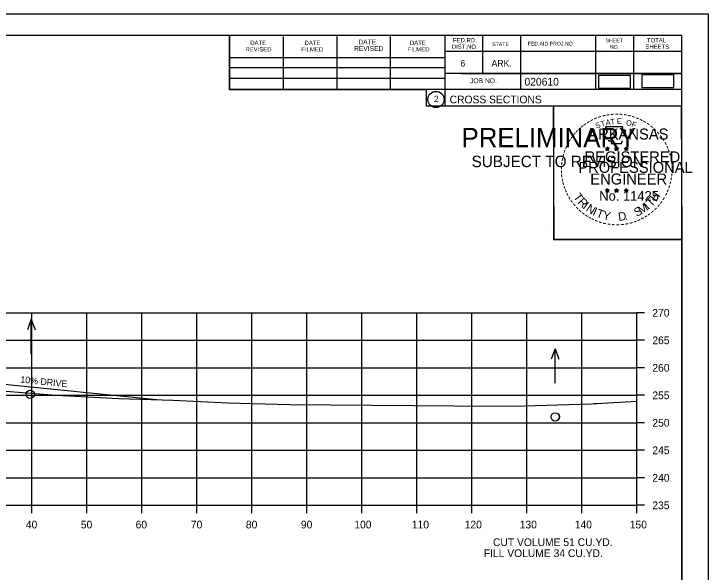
# Model space of a CAD drawing. Extents: x 1103485 to 1107180, y 2010593 to 2011873.
# Drawn here: x 1107053.9 to 1107180.1, y 2011344.7 to 2011446.2 of the extents above; entities that cross this region are included whole.
import ezdxf

# ---------------------------------------------------------------- set-up
doc = ezdxf.new("R2010")
doc.units = 0
for name, color, linetype in [('R_Axis', 7, 'Continuous'), ('R_Axis Annot', 7, 'Continuous'), ('R_Border', 7, 'Continuous'), ('R_Border PE', 7, 'Continuous'), ('R_Border Prem', 7, 'Continuous'), ('R_Drive', 7, 'Continuous'), ('R_Exist Surface', 7, 'Continuous'), ('R_Grid', 7, 'Continuous'), ('R_No Plot', 7, 'Continuous'), ('R_Water', 7, 'Continuous'), ('R_Water Annot', 7, 'Continuous')]:
    doc.layers.add(name, color=color, linetype=linetype)

msp = doc.modelspace()

# ---------------------------------------------------------------- linework, layer by layer
at = {"layer": 'R_Axis'}
for p, q in [((1107167.18, 2011356.83), (1107167.18, 2011391.83)), ((1107168.58, 2011391.83), (1107167.18, 2011391.83)), ((1107168.58, 2011386.83), (1107167.18, 2011386.83)), ((1107168.58, 2011381.83), (1107167.18, 2011381.83)), ((1107168.58, 2011376.83), (1107167.18, 2011376.83)), ((1107168.58, 2011371.83), (1107167.18, 2011371.83)), ((1107168.58, 2011366.83), (1107167.18, 2011366.83)), ((1107168.58, 2011361.83), (1107167.18, 2011361.83)), ((1106867.18, 2011356.83), (1107167.18, 2011356.83)), ((1107057.18, 2011355.43), (1107057.18, 2011356.83)), ((1107067.18, 2011355.43), (1107067.18, 2011356.83)), ((1107077.18, 2011355.43), (1107077.18, 2011356.83)), ((1107087.18, 2011355.43), (1107087.18, 2011356.83)), ((1107097.18, 2011355.43), (1107097.18, 2011356.83)), ((1107107.18, 2011355.43), (1107107.18, 2011356.83)), ((1107117.18, 2011355.43), (1107117.18, 2011356.83)), ((1107127.18, 2011355.43), (1107127.18, 2011356.83)), ((1107137.18, 2011355.43), (1107137.18, 2011356.83)), ((1107147.18, 2011355.43), (1107147.18, 2011356.83)), ((1107157.18, 2011355.43), (1107157.18, 2011356.83)), ((1107167.18, 2011355.43), (1107167.18, 2011356.83)), ((1107168.58, 2011356.83), (1107167.18, 2011356.83))]:
    msp.add_line(p, q, dxfattribs=at)
at = {"layer": 'R_Border'}
for p, q in [((1106859.18, 2011442.29), (1107175.36, 2011442.29)), ((1107093.1, 2011432.41), (1107093.1, 2011442.29)), ((1107102.96, 2011432.41), (1107102.96, 2011442.09)), ((1107112.72, 2011432.41), (1107112.72, 2011442.09)), ((1107122.4, 2011432.41), (1107122.4, 2011442.09)), ((1107132.26, 2011442.29), (1107132.26, 2011429.49)), ((1107139.1, 2011442.29), (1107139.1, 2011435.35)), ((1107146.04, 2011442.29), (1107146.04, 2011432.41)), ((1107159.62, 2011442.29), (1107159.62, 2011432.41)), ((1107166.56, 2011442.29), (1107166.56, 2011432.41)), ((1107175.36, 2011236.83), (1107175.36, 2011442.29)), ((1107175.36, 2011439.35), (1107132.26, 2011439.35)), ((1107175.36, 2011439.37), (1107175.36, 2011439.37)), ((1107093.1, 2011438.27), (1107132.26, 2011438.27)), ((1107093.1, 2011436.41), (1107132.26, 2011436.41)), ((1107175.36, 2011435.35), (1107132.26, 2011435.35)), ((1107135.22, 2011435.35), (1107175.36, 2011435.35)), ((1107093.1, 2011432.41), (1107093.1, 2011434.47)), ((1107093.1, 2011434.47), (1107132.26, 2011434.47)), ((1107175.36, 2011432.41), (1107093.1, 2011432.41)), ((1107132.26, 2011429.49), (1107175.36, 2011429.49))]:
    msp.add_line(p, q, dxfattribs=at)
msp.add_circle((1107130.65, 2011430.63), 1.47, dxfattribs=at)
at = {"layer": 'R_Border PE'}
for p, q in [((1107161.45, 2011421.75), (1107161.8, 2011421.63)), ((1107161.45, 2011421.75), (1107161.7, 2011421.7)), ((1107161.45, 2011421.75), (1107161.69, 2011421.62)), ((1107161.58, 2011421.34), (1107161.8, 2011421.63)), ((1107161.58, 2011421.34), (1107161.71, 2011421.58)), ((1107161.58, 2011421.34), (1107161.8, 2011421.55)), ((1107161.8, 2011422), (1107161.76, 2011421.75)), ((1107161.8, 2011421.63), (1107161.8, 2011422)), ((1107161.8, 2011422), (1107161.85, 2011421.75)), ((1107162.14, 2011421.75), (1107161.8, 2011421.63)), ((1107162.01, 2011421.34), (1107161.8, 2011421.63)), ((1107162.01, 2011421.34), (1107161.8, 2011421.55)), ((1107162.14, 2011421.75), (1107161.86, 2011421.7)), ((1107162.01, 2011421.34), (1107161.87, 2011421.63)), ((1107162.14, 2011421.75), (1107161.94, 2011421.64)), ((1107163.12, 2011421.75), (1107163.47, 2011421.63)), ((1107163.12, 2011421.75), (1107163.37, 2011421.7)), ((1107163.12, 2011421.75), (1107163.36, 2011421.62)), ((1107163.25, 2011421.34), (1107163.47, 2011421.63)), ((1107163.25, 2011421.34), (1107163.38, 2011421.58)), ((1107163.25, 2011421.34), (1107163.47, 2011421.55)), ((1107163.47, 2011422), (1107163.43, 2011421.75)), ((1107163.47, 2011421.63), (1107163.47, 2011422)), ((1107163.47, 2011422), (1107163.52, 2011421.75)), ((1107163.81, 2011421.75), (1107163.47, 2011421.63)), ((1107163.68, 2011421.34), (1107163.47, 2011421.63)), ((1107163.68, 2011421.34), (1107163.47, 2011421.55)), ((1107163.81, 2011421.75), (1107163.53, 2011421.7)), ((1107163.68, 2011421.34), (1107163.54, 2011421.63)), ((1107163.81, 2011421.75), (1107163.61, 2011421.64)), ((1107164.88, 2011421.73), (1107165.23, 2011421.62)), ((1107164.88, 2011421.73), (1107165.14, 2011421.69)), ((1107164.88, 2011421.73), (1107165.12, 2011421.61)), ((1107165.02, 2011421.33), (1107165.23, 2011421.62)), ((1107165.02, 2011421.33), (1107165.14, 2011421.57)), ((1107165.02, 2011421.33), (1107165.23, 2011421.54)), ((1107165.23, 2011421.99), (1107165.19, 2011421.74)), ((1107165.23, 2011421.62), (1107165.23, 2011421.99)), ((1107165.23, 2011421.99), (1107165.28, 2011421.74)), ((1107165.58, 2011421.73), (1107165.23, 2011421.62)), ((1107165.44, 2011421.33), (1107165.23, 2011421.62)), ((1107165.44, 2011421.33), (1107165.23, 2011421.54)), ((1107165.58, 2011421.73), (1107165.29, 2011421.68)), ((1107165.44, 2011421.33), (1107165.31, 2011421.62)), ((1107165.58, 2011421.73), (1107165.37, 2011421.63)), ((1107161.44, 2011414.17), (1107161.79, 2011414.06)), ((1107161.44, 2011414.17), (1107161.7, 2011414.13)), ((1107161.44, 2011414.17), (1107161.68, 2011414.05)), ((1107161.58, 2011413.76), (1107161.79, 2011414.06)), ((1107161.58, 2011413.76), (1107161.7, 2011414.01)), ((1107161.58, 2011413.76), (1107161.79, 2011413.98)), ((1107161.79, 2011414.43), (1107161.75, 2011414.17)), ((1107161.79, 2011414.06), (1107161.79, 2011414.43)), ((1107161.79, 2011414.43), (1107161.84, 2011414.18)), ((1107162.14, 2011414.17), (1107161.79, 2011414.06)), ((1107162.01, 2011413.76), (1107161.79, 2011414.06)), ((1107162.01, 2011413.76), (1107161.79, 2011413.98)), ((1107162.14, 2011414.17), (1107161.85, 2011414.12)), ((1107162.01, 2011413.76), (1107161.87, 2011414.06)), ((1107162.14, 2011414.17), (1107161.94, 2011414.07)), ((1107163.11, 2011414.17), (1107163.46, 2011414.06)), ((1107163.11, 2011414.17), (1107163.37, 2011414.13)), ((1107163.11, 2011414.17), (1107163.35, 2011414.05)), ((1107163.25, 2011413.76), (1107163.46, 2011414.06)), ((1107163.25, 2011413.76), (1107163.37, 2011414.01)), ((1107163.25, 2011413.76), (1107163.46, 2011413.98)), ((1107163.46, 2011414.43), (1107163.42, 2011414.17)), ((1107163.46, 2011414.06), (1107163.46, 2011414.43)), ((1107163.46, 2011414.43), (1107163.51, 2011414.18)), ((1107163.81, 2011414.17), (1107163.46, 2011414.06)), ((1107163.68, 2011413.76), (1107163.46, 2011414.06)), ((1107163.68, 2011413.76), (1107163.46, 2011413.98)), ((1107163.81, 2011414.17), (1107163.52, 2011414.12)), ((1107163.68, 2011413.76), (1107163.54, 2011414.06)), ((1107163.81, 2011414.17), (1107163.61, 2011414.07)), ((1107164.88, 2011414.16), (1107165.23, 2011414.05)), ((1107164.88, 2011414.16), (1107165.13, 2011414.12)), ((1107164.88, 2011414.16), (1107165.12, 2011414.04)), ((1107165.01, 2011413.75), (1107165.23, 2011414.05)), ((1107165.01, 2011413.75), (1107165.14, 2011414)), ((1107165.01, 2011413.75), (1107165.23, 2011413.97)), ((1107165.23, 2011414.42), (1107165.19, 2011414.16)), ((1107165.23, 2011414.05), (1107165.23, 2011414.42)), ((1107165.23, 2011414.42), (1107165.28, 2011414.17)), ((1107165.58, 2011414.16), (1107165.23, 2011414.05)), ((1107165.44, 2011413.75), (1107165.23, 2011414.05)), ((1107165.44, 2011413.75), (1107165.23, 2011413.97)), ((1107165.58, 2011414.16), (1107165.29, 2011414.11)), ((1107165.44, 2011413.75), (1107165.31, 2011414.05)), ((1107165.58, 2011414.16), (1107165.37, 2011414.06))]:
    msp.add_line(p, q, dxfattribs=at)
for points in [[(1107161.49, 2011425.62), (1107161.76, 2011424.8)], [(1107165, 2011424.7), (1107165.14, 2011424.99), (1107164.46, 2011424.96), (1107164.61, 2011425.62), (1107161.49, 2011425.62)], [(1107161.98, 2011423.2), (1107161.98, 2011423.11), (1107162.54, 2011423.09), (1107162.49, 2011422.62), (1107164.36, 2011422.62), (1107164.56, 2011423.16)], [(1107161.8, 2011422), (1107162.01, 2011421.34), (1107161.45, 2011421.75), (1107162.14, 2011421.75), (1107161.58, 2011421.34), (1107161.8, 2011422)], [(1107163.47, 2011422), (1107163.68, 2011421.34), (1107163.12, 2011421.75), (1107163.81, 2011421.75), (1107163.25, 2011421.34), (1107163.47, 2011422)], [(1107165.23, 2011421.99), (1107165.44, 2011421.33), (1107164.88, 2011421.73), (1107165.58, 2011421.73), (1107165.02, 2011421.33), (1107165.23, 2011421.99)], [(1107161.79, 2011414.43), (1107162.01, 2011413.76), (1107161.44, 2011414.17), (1107162.14, 2011414.17), (1107161.58, 2011413.76), (1107161.79, 2011414.43)], [(1107163.46, 2011414.43), (1107163.68, 2011413.76), (1107163.11, 2011414.17), (1107163.81, 2011414.17), (1107163.25, 2011413.76), (1107163.46, 2011414.43)], [(1107165.23, 2011414.42), (1107165.44, 2011413.75), (1107164.88, 2011414.16), (1107165.58, 2011414.16), (1107165.01, 2011413.75), (1107165.23, 2011414.42)]]:
    msp.add_lwpolyline(points, dxfattribs=at)
for centre, radius in [((1107161.8, 2011421.63), 0.172), ((1107161.8, 2011421.63), 0.145), ((1107161.8, 2011421.63), 0.116), ((1107161.8, 2011421.63), 0.0991), ((1107161.8, 2011421.63), 0.0747), ((1107161.8, 2011421.63), 0.0495), ((1107161.8, 2011421.63), 0.0296), ((1107163.47, 2011421.63), 0.172), ((1107163.47, 2011421.63), 0.145), ((1107163.47, 2011421.63), 0.116), ((1107163.47, 2011421.63), 0.0991), ((1107163.47, 2011421.63), 0.0747), ((1107163.47, 2011421.63), 0.0495), ((1107163.47, 2011421.63), 0.0296), ((1107165.23, 2011421.62), 0.172), ((1107165.23, 2011421.62), 0.145), ((1107165.23, 2011421.62), 0.116), ((1107165.23, 2011421.62), 0.0991), ((1107165.23, 2011421.62), 0.0747), ((1107165.23, 2011421.62), 0.0495), ((1107165.23, 2011421.62), 0.0296), ((1107161.79, 2011414.06), 0.172), ((1107161.79, 2011414.06), 0.145), ((1107161.79, 2011414.06), 0.116), ((1107161.79, 2011414.06), 0.0991), ((1107161.79, 2011414.06), 0.0747), ((1107161.79, 2011414.06), 0.0495), ((1107161.79, 2011414.06), 0.0296), ((1107163.46, 2011414.06), 0.172), ((1107163.46, 2011414.06), 0.145), ((1107163.46, 2011414.06), 0.116), ((1107163.46, 2011414.06), 0.0991), ((1107163.46, 2011414.06), 0.0747), ((1107163.46, 2011414.06), 0.0495), ((1107163.46, 2011414.06), 0.0296), ((1107165.23, 2011414.05), 0.172), ((1107165.23, 2011414.05), 0.145), ((1107165.23, 2011414.05), 0.116), ((1107165.23, 2011414.05), 0.0991), ((1107165.23, 2011414.05), 0.0747), ((1107165.23, 2011414.05), 0.0495), ((1107165.23, 2011414.05), 0.0296)]:
    msp.add_circle(centre, radius, dxfattribs=at)
at = {"layer": 'R_Drive'}
msp.add_line((1107048.15, 2011379.23), (1107079.85, 2011376.06), dxfattribs=at)
at = {"layer": 'R_Exist Surface'}
msp.add_lwpolyline([(1107052.48, 2011377.58), (1107061.61, 2011376.83), (1107073.02, 2011376.26), (1107082.8, 2011375.98), (1107092.86, 2011375.49), (1107104.07, 2011375.18), (1107111.47, 2011375.09), (1107118.92, 2011375.06), (1107126.74, 2011374.96), (1107133.89, 2011374.94), (1107144.71, 2011374.88), (1107148.68, 2011374.96), (1107158.92, 2011375.31), (1107159.41, 2011375.33), (1107159.82, 2011375.36), (1107159.9, 2011375.37), (1107167.18, 2011375.79)], dxfattribs=at)
at = {"layer": 'R_Grid'}
for p, q in [((1106867.18, 2011391.83), (1107167.18, 2011391.83)), ((1107057.18, 2011356.83), (1107057.18, 2011391.83)), ((1107067.18, 2011356.83), (1107067.18, 2011391.83)), ((1107077.18, 2011356.83), (1107077.18, 2011391.83)), ((1107087.18, 2011356.83), (1107087.18, 2011391.83)), ((1107097.18, 2011356.83), (1107097.18, 2011391.83)), ((1107107.18, 2011356.83), (1107107.18, 2011391.83)), ((1107117.18, 2011356.83), (1107117.18, 2011391.83)), ((1107127.18, 2011356.83), (1107127.18, 2011391.83)), ((1107137.18, 2011356.83), (1107137.18, 2011391.83)), ((1107147.18, 2011356.83), (1107147.18, 2011391.83)), ((1107157.18, 2011356.83), (1107157.18, 2011391.83)), ((1107167.18, 2011356.83), (1107167.18, 2011391.83)), ((1106867.18, 2011386.83), (1107167.18, 2011386.83)), ((1106867.18, 2011381.83), (1107167.18, 2011381.83)), ((1106867.18, 2011376.83), (1107167.18, 2011376.83)), ((1106867.18, 2011371.83), (1107167.18, 2011371.83)), ((1106867.18, 2011366.83), (1107167.18, 2011366.83)), ((1106867.18, 2011361.83), (1107167.18, 2011361.83)), ((1106867.18, 2011356.83), (1107167.18, 2011356.83))]:
    msp.add_line(p, q, dxfattribs=at)
at = {"layer": 'R_No Plot'}
for p, q in [((1106846.78, 2011446.19), (1107180.12, 2011446.19)), ((1107151.4, 2011407.04), (1107151.4, 2011407.04))]:
    msp.add_line(p, q, dxfattribs=at)
for points in [[(1106846.78, 2011446.19), (1107180.12, 2011446.19), (1107180.12, 2011232.85), (1106846.78, 2011232.85)], [(1107093.1, 2011442.29), (1107093.1, 2011432.41), (1107128.84, 2011432.41), (1107128.84, 2011429.49), (1107152.04, 2011429.49), (1107152.04, 2011405.16), (1107175.36, 2011405.16), (1107175.36, 2011236.83), (1106859.18, 2011236.83), (1106859.18, 2011442.29)], [(1107152.04, 2011429.49), (1107175.24, 2011429.49), (1107175.36, 2011405.16), (1107152.16, 2011405.16)]]:
    msp.add_lwpolyline(points, close=True, dxfattribs=at)
at = {"layer": 'R_Water'}
for points in [[(1107168.04, 2011432.78), (1107173.87, 2011432.78), (1107173.87, 2011435.1), (1107168.04, 2011435.1)], [(1107160.2, 2011432.68), (1107166.03, 2011432.68), (1107166.03, 2011434.99), (1107160.2, 2011434.99)]]:
    msp.add_lwpolyline(points, close=True, dxfattribs=at)
for centre, radius in [((1107056.91, 2011377.02), 0.755), ((1107056.91, 2011377.02), 0.75), ((1107152.32, 2011372.91), 0.755), ((1107152.32, 2011372.91), 0.75)]:
    msp.add_circle(centre, radius, dxfattribs=at)
at = {"layer": 'R_Water Annot'}
for p, q in [((1107057.09, 2011390.65), (1107056.39, 2011388.72)), ((1107057.09, 2011384.36), (1107057.09, 2011390.65)), ((1107057.09, 2011390.65), (1107057.79, 2011388.72)), ((1107152.3, 2011385.3), (1107151.6, 2011383.38)), ((1107152.3, 2011379.02), (1107152.3, 2011385.3)), ((1107152.3, 2011385.3), (1107153, 2011383.38))]:
    msp.add_line(p, q, dxfattribs=at)

# ---------------------------------------------------------------- texts
at = {"layer": 'R_Axis Annot'}
for s, p in [('270', (1107169.98, 2011391.13)), ('265', (1107169.98, 2011386.13)), ('260', (1107169.98, 2011381.13)), ('255', (1107169.98, 2011376.13)), ('250', (1107169.98, 2011371.13)), ('245', (1107169.98, 2011366.13)), ('240', (1107169.98, 2011361.13)), ('235', (1107169.98, 2011356.13)), ('40', (1107056.1, 2011352.63)), ('50', (1107066.1, 2011352.63)), ('60', (1107076.06, 2011352.63)), ('70', (1107086.1, 2011352.63)), ('80', (1107096.1, 2011352.63)), ('90', (1107106.1, 2011352.63)), ('100', (1107115.81, 2011352.63)), ('110', (1107126.26, 2011352.63)), ('120', (1107135.87, 2011352.63)), ('130', (1107145.87, 2011352.63)), ('140', (1107155.87, 2011352.63)), ('150', (1107165.87, 2011352.63)), ('CUT VOLUME 51 CU.YD.', (1107141.01, 2011349.43)), ('FILL VOLUME 34 CU.YD.', (1107139.34, 2011347.43))]:
    msp.add_text(s, height=1.4, dxfattribs=at).set_placement(p)
at = {"layer": 'R_Border'}
for s, height, p in [('DATE', 0.879, (1107116.54, 2011440.63)), ('FED.RD.', 0.782, (1107133.74, 2011441.01)), ('SHEET', 0.684, (1107161.48, 2011441.01)), ('TOTAL', 0.782, (1107169, 2011441.01)), ('REVISED', 0.782, (1107096.02, 2011439.35)), ('DATE', 0.782, (1107096.9, 2011440.53)), ('FILMED', 0.782, (1107106.18, 2011439.35)), ('DATE', 0.782, (1107106.76, 2011440.53)), ('REVISED', 0.879, (1107115.76, 2011439.45)), ('FILMED', 0.782, (1107125.52, 2011439.35)), ('DATE', 0.782, (1107125.92, 2011440.53)), ('DIST.NO.', 0.782, (1107133.54, 2011439.83)), ('STATE', 0.684, (1107140.86, 2011440.33)), ('FED.AID PROJ.NO.', 0.684, (1107147.32, 2011440.43)), ('NO.', 0.684, (1107162.26, 2011439.83)), ('SHEETS', 0.782, (1107168.72, 2011439.83)), ('6', 1.17, (1107135.1, 2011436.61)), ('ARK.', 1.172, (1107140.76, 2011436.61)), ('JOB NO.', 0.879, (1107136.86, 2011433.59)), ('020610', 1.4, (1107146.74, 2011433.15)), ('2', 1.17, (1107130.27, 2011430.14)), ('CROSS SECTIONS', 1.4, (1107133.13, 2011429.92))]:
    msp.add_text(s, height=height, rotation=360, dxfattribs=at).set_placement(p)
at = {"layer": 'R_Border PE'}
for s, height, rotation, p in [('-', 1.6, 19.1761, (1107160.24, 2011426.75)), ('-', 1.6, 13.6301, (1107160.99, 2011426.99)), ('-', 1.6, 10.2193, (1107161.67, 2011427.15)), ('-', 1.6, 5.8968, (1107162.39, 2011427.26)), ('-', 1.6, 0.1862, (1107163.17, 2011427.34)), ('-', 1.6, 357.743, (1107163.89, 2011427.32)), ('-', 1.6, 352.1617, (1107164.63, 2011427.27)), ('-', 1.6, 347.2049, (1107165.35, 2011427.15)), ('-', 1.6, 342.3362, (1107165.99, 2011427)), ('-', 1.6, 36.2317, (1107157.8, 2011425.4)), ('-', 1.6, 34.0636, (1107158.37, 2011425.79)), ('-', 1.6, 28.7918, (1107158.97, 2011426.16)), ('-', 1.6, 24.3072, (1107159.6, 2011426.48)), ('S', 1, 21.594, (1107159.84, 2011425.3)), ('T', 1, 16.4036, (1107160.76, 2011425.63)), ('A', 1, 11.2132, (1107161.58, 2011425.88)), ('T', 1, 6.0228, (1107162.43, 2011426.05)), ('E', 1, 0.8323, (1107163.54, 2011426.16)), ('O', 1, 350.4515, (1107165.14, 2011425.95)), ('F', 1, 340.0707, (1107166.1, 2011425.72)), ('-', 1.6, 337.8551, (1107166.72, 2011426.77)), ('-', 1.6, 334.1211, (1107167.35, 2011426.5)), ('-', 1.6, 329.6409, (1107167.93, 2011426.22)), ('-', 1.6, 325.8627, (1107168.58, 2011425.86)), ('-', 1.6, 48.423, (1107156.44, 2011424.13)), ('-', 1.6, 42.9622, (1107156.89, 2011424.6)), ('-', 1.6, 38.9507, (1107157.32, 2011425.02)), ('ARKANSAS', 2, 360, (1107158.34, 2011423.34)), ('-', 1.6, 320.5297, (1107169.19, 2011425.43)), ('-', 1.6, 315.5786, (1107169.78, 2011424.95)), ('-', 1.6, 54.2325, (1107155.62, 2011423.07)), ('-', 1.6, 50.6142, (1107156.04, 2011423.64)), ('-', 1.6, 309.8797, (1107170.35, 2011424.4)), ('-', 1.6, 306.6522, (1107170.88, 2011423.79)), ('-', 1.6, 62.8713, (1107154.98, 2011421.93)), ('-', 1.6, 58.0706, (1107155.3, 2011422.55)), ('-', 1.4, 303.6753, (1107171.36, 2011423.23)), ('-', 1.6, 299.6684, (1107171.68, 2011422.62)), ('-', 1.6, 72.3945, (1107154.51, 2011420.69)), ('-', 1.6, 67.7743, (1107154.73, 2011421.32)), ('REGISTERED', 2, 360, (1107157.66, 2011419.19)), ('DWB', 0.01, 360, (1107161.78, 2011421.63)), ('DWB', 0.01, 360, (1107163.45, 2011421.63)), ('DWB', 0.01, 360, (1107165.22, 2011421.62)), ('-', 1.6, 294.6628, (1107172.01, 2011422.01)), ('-', 1.6, 290.5728, (1107172.26, 2011421.43)), ('-', 1.6, 81.2013, (1107154.18, 2011419.26)), ('-', 1.6, 75.461, (1107154.31, 2011419.98)), ('-', 1.6, 285.1233, (1107172.5, 2011420.85)), ('-', 1.6, 280.5493, (1107172.7, 2011420.11)), ('-', 1.6, 85.1863, (1107154.1, 2011418.57)), ('PROFESSIONAL', 2, 360, (1107156.52, 2011417.28)), ('-', 1.6, 276.5962, (1107172.86, 2011419.34)), ('-', 1.6, 94.1959, (1107154.11, 2011417.15)), ('-', 1.6, 89.0622, (1107154.08, 2011417.87)), ('-', 1.6, 274.3301, (1107172.92, 2011418.62)), ('-', 1.6, 269.9407, (1107172.95, 2011417.99)), ('-', 1.6, 98.9479, (1107154.18, 2011416.48)), ('-', 1.6, 101.7149, (1107154.32, 2011415.75)), ('ENGINEER', 2, 360, (1107158.7, 2011415.16)), ('-', 1.6, 260.9953, (1107172.86, 2011416.67)), ('-', 1.6, 263.5172, (1107172.94, 2011417.32)), ('-', 1.6, 105.4578, (1107154.48, 2011415.15)), ('-', 1.6, 109.0874, (1107154.7, 2011414.52)), ('-', 1.6, 252.8681, (1107172.57, 2011415.27)), ('-', 1.6, 255.7626, (1107172.75, 2011415.99)), ('-', 1.6, 114.0643, (1107154.95, 2011413.93)), ('-', 1.6, 115.7289, (1107155.25, 2011413.31)), ('T', 1.54, 306.0406, (1107155.55, 2011412.9)), ('No. 11425', 1.757, 360, (1107160.33, 2011412.21)), ('DWB', 0.01, 360, (1107161.78, 2011414.06)), ('DWB', 0.01, 360, (1107163.45, 2011414.06)), ('DWB', 0.01, 360, (1107165.22, 2011414.05)), ('H', 1.54, 54.6088, (1107170.67, 2011411.94)), ('-', 1.6, 244.6197, (1107172.09, 2011413.97)), ('-', 1.6, 247.8887, (1107172.35, 2011414.59)), ('-', 1.6, 120.4471, (1107155.61, 2011412.72)), ('-', 1.6, 125.8934, (1107156.01, 2011412.16)), ('R', 1.54, 314.005, (1107156.32, 2011411.85)), ('T', 1.54, 46.6444, (1107169.78, 2011410.99)), ('-', 1.6, 239.0712, (1107171.69, 2011413.21)), ('-', 1.6, 130.7181, (1107156.48, 2011411.61)), ('-', 1.6, 134.2238, (1107156.99, 2011411.06)), ('I', 1.54, 321.9694, (1107157.22, 2011410.92)), ('N', 1.54, 326.5002, (1107157.78, 2011410.45)), ('S', 1.54, 26.9312, (1107167.1, 2011409.26)), ('M', 1.54, 32.6563, (1107167.94, 2011409.67)), ('I', 1.54, 42.1136, (1107169.22, 2011410.51)), ('-', 1.6, 231.2538, (1107170.86, 2011411.99)), ('-', 1.6, 233.8452, (1107171.29, 2011412.56)), ('-', 1.6, 138.9338, (1107157.52, 2011410.6)), ('-', 1.6, 144.6463, (1107158.07, 2011410.19)), ('I', 1.54, 335.3603, (1107158.99, 2011409.66)), ('T', 1.54, 339.8912, (1107159.65, 2011409.34)), ('Y', 1.54, 347.8556, (1107160.87, 2011408.89)), ('D', 1.54, 6.3969, (1107163.85, 2011408.53)), ('-', 1.6, 215.7363, (1107169.31, 2011410.45)), ('-', 1.6, 221.0851, (1107169.86, 2011410.92)), ('-', 1.6, 225.7653, (1107170.38, 2011411.43)), ('-', 1.6, 148.0898, (1107158.64, 2011409.82)), ('-', 1.6, 151.5704, (1107159.21, 2011409.5)), ('-', 1.6, 154.6002, (1107159.74, 2011409.25)), ('-', 1.6, 158.5612, (1107160.36, 2011409)), ('.', 1.54, 13.7642, (1107165.05, 2011408.66)), ('-', 1.6, 200.7184, (1107166.98, 2011409.12)), ('-', 1.6, 204.2516, (1107167.6, 2011409.4)), ('-', 1.6, 207.3568, (1107168.22, 2011409.72)), ('-', 1.6, 212.2491, (1107168.78, 2011410.06)), ('-', 1.6, 162.7983, (1107161.05, 2011408.78)), ('-', 1.6, 167.5555, (1107161.76, 2011408.62)), ('-', 1.6, 173.1155, (1107162.53, 2011408.51)), ('-', 1.6, 176.5183, (1107163.28, 2011408.46)), ('-', 1.6, 181.5918, (1107164.03, 2011408.48)), ('-', 1.6, 185.8167, (1107164.84, 2011408.55)), ('-', 1.6, 191.2858, (1107165.57, 2011408.68)), ('-', 1.6, 195.4743, (1107166.3, 2011408.88))]:
    msp.add_text(s, height=height, rotation=rotation, dxfattribs=at).set_placement(p)
at = {"layer": 'R_Border Prem'}
for s, height, p in [('PRELIMINARY', 3.5, (1107135.31, 2011421.95)), ('DWB', 0.01, (1107136.06, 2011423.8)), ('SUBJECT TO REVISION', 2.0751, (1107137.12, 2011418.32))]:
    msp.add_text(s, height=height, rotation=360, dxfattribs=at).set_placement(p)
at = {"layer": 'R_Drive'}
msp.add_text('10% DRIVE', height=1.2, rotation=354.289, dxfattribs=at).set_placement((1107055.06, 2011379.14))

doc.saveas('drawing.dxf')
